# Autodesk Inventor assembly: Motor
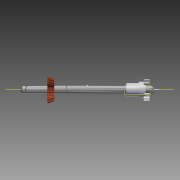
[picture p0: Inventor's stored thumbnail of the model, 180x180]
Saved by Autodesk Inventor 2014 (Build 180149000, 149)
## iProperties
Created: 2008-07
Part Number: Motor
Document SubType Name: Assembly
Designer: tangg
Mass: 130.161 g
Surface Area: 104.869 cm^2
Volume: 19.3028 cm^3
Density: 6.7431 g/cm^3
Author: tangg
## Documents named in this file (4)
- C:\Users\iTools\Desktop\tutorial files\Dynamic Simulation 1 and 2\Motor.iam
- C:\Users\iTools\Desktop\tutorial files\Dynamic Simulation 1 and 2\Motor shaft.ipt
- C:\Users\iTools\Desktop\tutorial files\Dynamic Simulation 1 and 2\Cooling fan.ipt
- C:\Users\iTools\Desktop\tutorial files\Dynamic Simulation 1 and 2\Bevel Gear11.ipt
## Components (3 placed, 3 different names)
1. Motor shaft:1 — Mate:1, Mate:2, Flush:1
2. Cooling fan:1 — Mate:1
3. Bevel Gear1:1 — Mate:2, Flush:1
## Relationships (3: Mate 2, Flush 1)
- Mate:1: Motor shaft:1 ↔ Cooling fan:1
- Mate:2: Motor shaft:1 ↔ Bevel Gear1:1
- Flush:1: Motor shaft:1 ↔ Bevel Gear1:1
